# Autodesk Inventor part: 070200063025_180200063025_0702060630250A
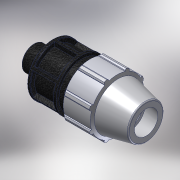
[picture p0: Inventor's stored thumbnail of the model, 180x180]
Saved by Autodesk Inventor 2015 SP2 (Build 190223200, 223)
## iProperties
Created: 2017-02
Part Number: 070200063025_180200063025_0702060630250A
Material: PVC-Piping
Description: PLASSON MALE ADAPTOR 63-2.1/2"
Document SubType Name: Modeling
Designer: KIM
Mass: 92.6774 g
Surface Area: 199.44 cm^2
Volume: 66.1981 cm^3
Density: 1.4 g/cm^3
Appearance: PTFE
Author: KIM
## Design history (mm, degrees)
derived "07020.ipt"
feature "Solid1::07020.ipt"
tag "TaggingFeature1"
body "Solid1"
other parameters: "d2" = 63, "d4" = 22.85714, "d7" = 113, "d8" = 84.75, "d9" = 22.85714, "d11" = 4.57143, "d12" = 90.4, "d13" = 120 deg, "d14" = 88.2, "d15" = 6 deg, "d16" = 101.7, "d18" = 3.15, "d19" = 35 deg, "d20" = 17.5 deg, "d21" = 105.09, "d23" = 0, "d25" = 360 deg, "d27" = 2.26, "d34" = 5.65, "d36" = 0, "d43" = 3.39, "d46" = 1.89, "d49" = 123, "d52" = 29, "d53" = 1.26, "d55" = 360 deg, "d57" = 75.184, "d58" = 52.6288, "d59" = 32, "d_" = 63, "E_" = 113, "l_" = 123, "l_2" = 29, "R_" = 75.184
